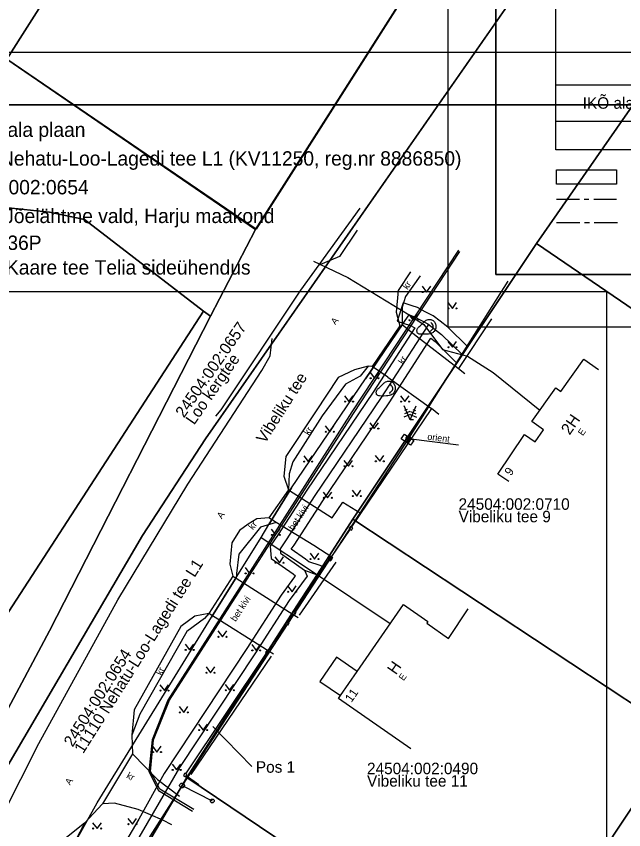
# Model space of a CAD drawing. Extents: x 553261 to 553443, y 6588794 to 6589074.
# Drawn here: x 553293.2 to 553356.6, y 6588861 to 6588946 of the extents above; entities that cross this region are included whole.
import ezdxf

# ---------------------------------------------------------------- set-up
doc = ezdxf.new("R2010")
doc.units = 0
for name, color, linetype in [('AED', 7, 'Continuous'), ('ELRAJATISMP', 7, 'Continuous'), ('HALJASTUS', 7, 'Continuous'), ('HOONE', 7, 'Continuous'), ('KASUTUSALA', 7, 'Continuous'), ('KPKAABEL', 7, 'Continuous'), ('MPKAABEL', 7, 'Continuous'), ('MPOHULIIN', 7, 'Continuous'), ('PIIR', 7, 'Continuous'), ('POST', 7, 'Continuous'), ('PR_SIDE', 7, 'Continuous'), ('PUU', 7, 'Continuous'), ('RELJEEF', 7, 'Continuous'), ('SITRASS', 7, 'Continuous'), ('TEE', 7, 'Continuous'), ('VORMISTUS', 7, 'Continuous'), ('VORMISTUS_1', 7, 'Continuous')]:
    doc.layers.add(name, color=color, linetype=linetype)

msp = doc.modelspace()

# ---------------------------------------------------------------- linework, layer by layer
at = {"layer": 'AED'}
for p, q in [((553326.069, 6588889.475), (553328.034, 6588892.392)), ((553325.826, 6588889.268), (553322.211, 6588883.814)), ((553321.522, 6588882.688), (553322.095, 6588883.54)), ((553319.487, 6588879.704), (553321.369, 6588882.436))]:
    msp.add_line(p, q, dxfattribs=at)
for points in [[(553342.795, 6588914.398), (553339.341, 6588909.194), (553339.996, 6588908.689)], [(553337.306, 6588904.401), (553336.512, 6588905.044), (553328.161, 6588892.658)], [(553319.28, 6588879.489), (553310.86, 6588866.886)], [(553310.919, 6588866.683), (553312.224, 6588865.754)]]:
    msp.add_lwpolyline(points, dxfattribs=at)
for points in [[(553328.057, 6588892.72), (553327.907, 6588892.467), (553328.16, 6588892.317), (553328.31, 6588892.57)], [(553325.947, 6588889.573), (553325.75, 6588889.33), (553325.994, 6588889.133), (553326.19, 6588889.376)], [(553321.969, 6588883.617), (553322.122, 6588883.868), (553322.373, 6588883.715), (553322.22, 6588883.464)], [(553321.244, 6588882.513), (553321.397, 6588882.764), (553321.648, 6588882.611), (553321.495, 6588882.36)], [(553319.386, 6588879.785), (553319.2, 6588879.553), (553319.401, 6588879.392), (553319.587, 6588879.623)], [(553310.768, 6588866.938), (553310.621, 6588866.68), (553310.845, 6588866.553), (553310.992, 6588866.811)]]:
    msp.add_lwpolyline(points, close=True, dxfattribs=at)
at = {"layer": 'ELRAJATISMP'}
for p, q in [((553334.079, 6588902.102), (553333.742, 6588901.609)), ((553334.303, 6588901.948), (553333.966, 6588901.456))]:
    msp.add_line(p, q, dxfattribs=at)
msp.add_lwpolyline([(553333.699, 6588902.363), (553334.684, 6588901.687), (553334.346, 6588901.195), (553333.361, 6588901.87)], close=True, dxfattribs=at)
at = {"layer": 'HALJASTUS'}
for p, q in [((553335.545, 6588917.799), (553336.008, 6588917.192)), ((553336.008, 6588917.192), (553336.454, 6588917.799)), ((553338.245, 6588916.088), (553338.708, 6588915.481)), ((553338.708, 6588915.481), (553339.154, 6588916.088)), ((553334.165, 6588914.857), (553334.628, 6588914.25)), ((553334.628, 6588914.25), (553335.074, 6588914.857)), ((553338.245, 6588912.035), (553338.708, 6588911.429)), ((553338.708, 6588911.429), (553339.154, 6588912.035)), ((553330.115, 6588908.793), (553330.578, 6588908.187)), ((553330.578, 6588908.187), (553331.024, 6588908.793)), ((553327.445, 6588906.362), (553327.908, 6588905.755)), ((553327.908, 6588905.755), (553328.354, 6588906.362)), ((553333.295, 6588906.362), (553333.758, 6588905.755)), ((553333.758, 6588905.755), (553334.204, 6588906.362)), ((553330.085, 6588903.54), (553330.548, 6588902.934)), ((553330.548, 6588902.934), (553330.994, 6588903.54)), ((553325.435, 6588903.21), (553325.898, 6588902.603)), ((553325.898, 6588902.603), (553326.344, 6588903.21)), ((553323.185, 6588900.088), (553323.648, 6588899.481)), ((553323.648, 6588899.481), (553324.094, 6588900.088)), ((553330.655, 6588900.118), (553331.118, 6588899.512)), ((553331.118, 6588899.512), (553331.564, 6588900.118)), ((553327.385, 6588899.608), (553327.848, 6588899.001)), ((553327.848, 6588899.001), (553328.294, 6588899.608)), ((553328.255, 6588896.486), (553328.718, 6588895.879)), ((553328.718, 6588895.879), (553329.164, 6588896.486)), ((553325.225, 6588896.306), (553325.688, 6588895.699)), ((553325.688, 6588895.699), (553326.134, 6588896.306)), ((553319.795, 6588892.434), (553320.258, 6588891.827)), ((553320.258, 6588891.827), (553320.704, 6588892.434)), ((553323.845, 6588889.912), (553324.308, 6588889.305)), ((553324.308, 6588889.305), (553324.754, 6588889.912)), ((553320.185, 6588889.522), (553320.648, 6588888.915)), ((553320.648, 6588888.915), (553321.094, 6588889.522)), ((553326.535, 6588888.988), (553322.728, 6588883.445)), ((553317.065, 6588888.411), (553317.528, 6588887.804)), ((553317.528, 6588887.804), (553317.974, 6588888.411)), ((553321.505, 6588886.49), (553321.968, 6588885.883)), ((553321.968, 6588885.883), (553322.414, 6588886.49)), ((553314.235, 6588881.789), (553314.698, 6588881.182)), ((553314.698, 6588881.182), (553315.144, 6588881.789)), ((553310.804, 6588880.425), (553311.268, 6588879.818)), ((553311.268, 6588879.818), (553311.713, 6588880.425)), ((553317.763, 6588880.369), (553318.227, 6588879.762)), ((553318.227, 6588879.762), (553318.672, 6588880.369)), ((553319.797, 6588879.161), (553311.403, 6588866.807)), ((553312.986, 6588878.038), (553313.449, 6588877.431)), ((553313.449, 6588877.431), (553313.895, 6588878.038)), ((553308.175, 6588876.172), (553308.638, 6588875.566)), ((553308.638, 6588875.566), (553309.084, 6588876.172)), ((553314.991, 6588876.208), (553315.454, 6588875.601)), ((553315.454, 6588875.601), (553315.9, 6588876.208)), ((553310.193, 6588873.89), (553310.656, 6588873.284)), ((553310.656, 6588873.284), (553311.102, 6588873.89)), ((553312.219, 6588872.047), (553312.682, 6588871.44)), ((553312.682, 6588871.44), (553313.128, 6588872.047)), ((553307.4, 6588869.743), (553307.863, 6588869.137)), ((553307.863, 6588869.137), (553308.309, 6588869.743)), ((553309.446, 6588867.886), (553309.91, 6588867.279)), ((553309.91, 6588867.279), (553310.355, 6588867.886)), ((553301.15, 6588861.764), (553301.613, 6588861.158)), ((553301.613, 6588861.158), (553302.059, 6588861.764)), ((553304.837, 6588862.218), (553305.3, 6588861.612)), ((553305.3, 6588861.612), (553305.746, 6588862.218))]:
    msp.add_line(p, q, dxfattribs=at)
for centre in [(553335.607, 6588917.192), (553336.436, 6588917.192), (553338.307, 6588915.481), (553339.136, 6588915.481), (553334.227, 6588914.25), (553335.056, 6588914.25), (553338.307, 6588911.429), (553339.136, 6588911.429), (553330.177, 6588908.187), (553331.006, 6588908.187), (553327.507, 6588905.755), (553328.336, 6588905.755), (553333.357, 6588905.755), (553334.186, 6588905.755), (553325.497, 6588902.603), (553326.326, 6588902.603), (553330.147, 6588902.934), (553330.976, 6588902.934), (553323.247, 6588899.481), (553324.076, 6588899.481), (553327.447, 6588899.001), (553328.276, 6588899.001), (553330.717, 6588899.512), (553331.546, 6588899.512), (553325.287, 6588895.699), (553326.116, 6588895.699), (553328.317, 6588895.879), (553329.146, 6588895.879), (553319.857, 6588891.827), (553320.686, 6588891.827), (553320.247, 6588888.915), (553321.076, 6588888.915), (553323.907, 6588889.305), (553324.736, 6588889.305), (553317.127, 6588887.804), (553317.956, 6588887.804), (553321.567, 6588885.883), (553322.396, 6588885.883), (553314.297, 6588881.182), (553315.126, 6588881.182), (553310.867, 6588879.818), (553311.696, 6588879.818), (553317.826, 6588879.762), (553318.654, 6588879.762), (553313.048, 6588877.431), (553313.877, 6588877.431), (553308.237, 6588875.566), (553309.066, 6588875.566), (553315.053, 6588875.601), (553315.882, 6588875.601), (553310.255, 6588873.284), (553311.084, 6588873.284), (553312.281, 6588871.44), (553313.11, 6588871.44), (553307.462, 6588869.137), (553308.291, 6588869.137), (553309.509, 6588867.279), (553310.337, 6588867.279), (553304.899, 6588861.612), (553305.728, 6588861.612), (553301.212, 6588861.158), (553302.041, 6588861.158)]:
    msp.add_circle(centre, 0.055, dxfattribs=at)
at = {"layer": 'HOONE'}
for points in [[(553344.6, 6588897.4), (553343.46, 6588898.16), (553346.25, 6588902.3), (553347.34, 6588901.56), (553348.22, 6588902.8), (553347, 6588903.67), (553349.51, 6588907.19), (553350.03, 6588906.81), (553352.44, 6588910.18), (553353.95, 6588909.1)], [(553334.38, 6588869.47), (553326.81, 6588874.73), (553327.02, 6588875.04), (553328.78, 6588877.57), (553333.6, 6588884.54), (553336.16, 6588882.78), (553336.03, 6588882.6), (553338.31, 6588881.02), (553340.37, 6588884.09)], [(553328.78, 6588877.57), (553326.61, 6588879.07), (553324.87, 6588876.53), (553327.02, 6588875.04)]]:
    msp.add_lwpolyline(points, dxfattribs=at)
at = {"layer": 'KASUTUSALA'}
msp.add_lwpolyline([(553298.589, 6588845.489), (553310.97, 6588866.48), (553318.933, 6588878.873), (553322.486, 6588884.402), (553325.143, 6588888.536), (553324.915, 6588888.615), (553323.722, 6588889.029), (553323.368, 6588889.281), (553321.889, 6588890.331), (553322.183, 6588890.765), (553325.191, 6588895.396), (553332.108, 6588905.636), (553336.471, 6588912.361), (553336.92, 6588912.017), (553339.047, 6588909.917), (553339.184, 6588909.781), (553340.314, 6588911.477), (553338.236, 6588913.528), (553337.435, 6588914.141), (553336.697, 6588914.706), (553335.876, 6588915.141), (553335.06, 6588915.573), (553334.508, 6588915.751), (553333.556, 6588916.059), (553332.941, 6588914.156), (553333.892, 6588913.849), (553334.278, 6588913.724), (553334.794, 6588913.451), (553330.44, 6588906.74), (553323.524, 6588896.5), (553320.516, 6588891.87), (553319.681, 6588890.636), (553319.806, 6588889.357), (553322.069, 6588887.75), (553322.329, 6588887.566), (553322.229, 6588887.43), (553320.837, 6588885.535), (553317.258, 6588879.965), (553308.612, 6588866.907), (553305.976, 6588862.143), (553296.944, 6588846.829)], dxfattribs=at)
at = {"layer": 'KPKAABEL'}
for points in [[(553339.343, 6588921.581), (553328.2, 6588904.67), (553309, 6588874.55), (553307.35, 6588870.42), (553307.02, 6588867.11), (553308.01, 6588865.12), (553311.573, 6588862.96)], [(553311.706, 6588863.143), (553308.18, 6588865.28), (553307.18, 6588867.11), (553307.51, 6588870.42), (553309.17, 6588874.55), (553328.37, 6588904.51), (553339.504, 6588921.413)]]:
    msp.add_lwpolyline(points, dxfattribs=at)
at = {"layer": 'MPKAABEL'}
msp.add_line((553334.121, 6588901.885), (553339.337, 6588901.229), dxfattribs=at)
msp.add_lwpolyline([(553329.039, 6588925.972), (553322.846, 6588917.405), (553314.535, 6588904.876), (553313.983, 6588904.237)], dxfattribs=at)
msp.add_lwpolyline([(553329.039, 6588925.972), (553322.846, 6588917.405), (553314.535, 6588904.876), (553313.983, 6588904.237)], dxfattribs=at)
at = {"layer": 'MPOHULIIN'}
msp.add_lwpolyline([(553344.514, 6588918.326), (553334.121, 6588901.885), (553310.484, 6588865.652), (553295.163, 6588841.482), (553297.428, 6588840.466)], dxfattribs=at)
at = {"layer": 'PIIR'}
for points in [[(553269.61, 6588823.387), (553275.1, 6588838.43), (553306.34, 6588891.77), (553312.93, 6588901.87), (553404.2, 6589032.89), (553408.34, 6589040.49)], [(553431.953, 6589028.538), (553426.41, 6589023.65), (553416.94, 6589023.42), (553405.24, 6589006.54), (553386.47, 6588978.82), (553366.97, 6588950.29), (553347.5, 6588922.26), (553328.32, 6588893.48), (553310.97, 6588866.48), (553295.9, 6588840.93), (553293.3, 6588836.47), (553287.77, 6588819.195)], [(553400.72, 6589027.895), (553312.93, 6588901.87), (553306.34, 6588891.77), (553275.1, 6588838.43), (553278.46, 6588847.64), (553296.63, 6588881.81), (553313.47, 6588914.66), (553318.15, 6588923.71), (553343.84, 6588964.11), (553353.8, 6588979.04), (553383.89, 6589024.22), (553386.338, 6589027.895)], [(553269.61, 6588964.599), (553291.21, 6588997.51), (553317.25, 6588980.99), (553292.18, 6588941.51), (553269.61, 6588957.599)], [(553269.61, 6588957.599), (553292.18, 6588941.51), (553318.15, 6588923.71), (553313.47, 6588914.66), (553312.72, 6588915.18), (553300.31, 6588924.76), (553296.64, 6588925.52), (553288.66, 6588926.39), (553273.87, 6588927.17), (553269.61, 6588927.473)], [(553269.61, 6588852.643), (553283.01, 6588869.39), (553312.72, 6588915.18), (553313.47, 6588914.66), (553296.63, 6588881.81), (553278.46, 6588847.64), (553269.61, 6588823.387)], [(553321.735, 6588819.195), (553313.8, 6588823.92), (553293.3, 6588836.47), (553295.9, 6588840.93), (553310.97, 6588866.48), (553344.52, 6588843.86), (553348.48, 6588841.22), (553333.312, 6588819.195)]]:
    msp.add_lwpolyline(points, dxfattribs=at)
for points in [[(553343.85, 6588964.09), (553318.22, 6588923.75), (553292.18, 6588941.51), (553317.25, 6588980.99)], [(553401.3, 6588927.47), (553381.71, 6588898.9), (553347.5, 6588922.26), (553366.97, 6588950.29)], [(553273.87, 6588927.17), (553288.66, 6588926.39), (553296.64, 6588925.52), (553300.31, 6588924.76), (553312.72, 6588915.18), (553283.01, 6588869.39), (553270.78, 6588864.58)], [(553347.5, 6588922.26), (553381.71, 6588898.9), (553362.44, 6588870.9), (553328.32, 6588893.48)], [(553362.44, 6588870.9), (553344.52, 6588843.86), (553310.97, 6588866.48), (553328.32, 6588893.48)], [(553362.44, 6588870.9), (553393.72, 6588849.46), (553375.51, 6588823.13), (553344.52, 6588843.86)]]:
    msp.add_lwpolyline(points, close=True, dxfattribs=at)
at = {"layer": 'POST'}
msp.add_lwpolyline([(553310.484, 6588865.652), (553313.644, 6588864.04)], dxfattribs=at)
for centre, radius in [((553334.121, 6588901.885), 0.25), ((553310.484, 6588865.652), 0.25), ((553313.644, 6588864.04), 0.2)]:
    msp.add_circle(centre, radius, dxfattribs=at)
at = {"layer": 'PR_SIDE'}
for points in [[(553334.2, 6588914.8), (553334.669, 6588914.648), (553336.156, 6588913.861)], [(553336.156, 6588913.861), (553336.152, 6588913.706), (553331.274, 6588906.188), (553324.358, 6588895.948), (553321.349, 6588891.317), (553320.712, 6588890.375), (553320.757, 6588889.908), (553323.26, 6588888.131)], [(553336.156, 6588913.861), (553337.578, 6588912.772), (553339.749, 6588910.629)], [(553323.26, 6588888.131), (553323.539, 6588887.524), (553321.662, 6588884.968), (553318.096, 6588879.419), (553310.213, 6588867.527), (553305.363, 6588859.136), (553297.678, 6588846.105), (553295.174, 6588844.041), (553294.134, 6588842.531), (553294.155, 6588836.433), (553294.55, 6588836.03), (553295.658, 6588835.332), (553307.558, 6588828.466)], [(553323.26, 6588888.131), (553324.587, 6588887.671)]]:
    msp.add_lwpolyline(points, dxfattribs=at)
at = {"layer": 'PUU'}
for p, q in [((553334.298, 6588903.859), (553333.677, 6588905.307)), ((553334.002, 6588904.929), (553333.726, 6588904.811)), ((553334.298, 6588903.859), (553334.919, 6588905.307)), ((553334.594, 6588904.929), (553334.869, 6588904.811)), ((553334.298, 6588904.403), (553333.641, 6588904.122)), ((553334.258, 6588904.713), (553333.707, 6588904.476)), ((553334.298, 6588904.403), (553334.954, 6588904.122)), ((553334.337, 6588904.713), (553334.889, 6588904.476)), ((553334.658, 6588903.859), (553334.298, 6588903.859))]:
    msp.add_line(p, q, dxfattribs=at)
at = {"layer": 'RELJEEF'}
for points in [[(553335.004, 6588913.178), (553335.023, 6588913.253), (553335.044, 6588913.318), (553335.067, 6588913.372), (553335.097, 6588913.429), (553335.148, 6588913.499), (553335.21, 6588913.562), (553335.296, 6588913.639), (553335.433, 6588913.765), (553335.523, 6588913.854), (553335.651, 6588913.986), (553335.723, 6588914.057), (553335.82, 6588914.141), (553335.896, 6588914.196), (553335.984, 6588914.25), (553336.093, 6588914.301), (553336.182, 6588914.327), (553336.278, 6588914.339), (553336.362, 6588914.335), (553336.448, 6588914.319), (553336.525, 6588914.295), (553336.625, 6588914.247), (553336.687, 6588914.208), (553336.769, 6588914.14), (553336.825, 6588914.08), (553336.883, 6588913.998), (553336.916, 6588913.936), (553336.948, 6588913.855), (553336.971, 6588913.771), (553336.983, 6588913.689), (553336.988, 6588913.605), (553336.985, 6588913.513), (553336.971, 6588913.418), (553336.946, 6588913.328), (553336.907, 6588913.234), (553336.865, 6588913.16), (553336.811, 6588913.087), (553336.752, 6588913.022), (553336.696, 6588912.974), (553336.623, 6588912.924), (553336.537, 6588912.881), (553336.463, 6588912.854), (553336.361, 6588912.828), (553336.225, 6588912.808), (553336.068, 6588912.793), (553335.77, 6588912.78), (553335.508, 6588912.779), (553335.351, 6588912.785), (553335.256, 6588912.798), (553335.183, 6588912.821), (553335.124, 6588912.853), (553335.077, 6588912.898), (553335.043, 6588912.954), (553335.021, 6588913.031), (553335.009, 6588913.106), (553335.004, 6588913.178)], [(553336.389, 6588913.048), (553336.432, 6588913.094), (553336.5, 6588913.167), (553336.568, 6588913.24), (553336.636, 6588913.314), (553336.692, 6588913.396), (553336.717, 6588913.492), (553336.717, 6588913.592), (553336.696, 6588913.689), (553336.654, 6588913.78), (553336.591, 6588913.857), (553336.525, 6588913.933), (553336.459, 6588914.008)], [(553330.763, 6588906.733), (553330.781, 6588906.807), (553330.803, 6588906.873), (553330.825, 6588906.926), (553330.856, 6588906.983), (553330.907, 6588907.054), (553330.969, 6588907.117), (553331.055, 6588907.194), (553331.192, 6588907.319), (553331.282, 6588907.409), (553331.41, 6588907.54), (553331.482, 6588907.612), (553331.579, 6588907.696), (553331.654, 6588907.75), (553331.743, 6588907.804), (553331.851, 6588907.855), (553331.941, 6588907.882), (553332.037, 6588907.893), (553332.12, 6588907.889), (553332.207, 6588907.873), (553332.283, 6588907.849), (553332.384, 6588907.802), (553332.445, 6588907.763), (553332.527, 6588907.695), (553332.584, 6588907.634), (553332.641, 6588907.552), (553332.674, 6588907.49), (553332.707, 6588907.409), (553332.729, 6588907.325), (553332.742, 6588907.244), (553332.747, 6588907.159), (553332.743, 6588907.068), (553332.729, 6588906.972), (553332.705, 6588906.883), (553332.666, 6588906.788), (553332.623, 6588906.714), (553332.57, 6588906.641), (553332.51, 6588906.577), (553332.455, 6588906.528), (553332.381, 6588906.479), (553332.296, 6588906.435), (553332.221, 6588906.408), (553332.119, 6588906.382), (553331.984, 6588906.362), (553331.826, 6588906.348), (553331.529, 6588906.334), (553331.266, 6588906.333), (553331.11, 6588906.339), (553331.015, 6588906.353), (553330.942, 6588906.375), (553330.883, 6588906.407), (553330.835, 6588906.452), (553330.802, 6588906.509), (553330.779, 6588906.586), (553330.768, 6588906.66), (553330.763, 6588906.733)], [(553332.148, 6588906.603), (553332.19, 6588906.648), (553332.259, 6588906.721), (553332.327, 6588906.794), (553332.394, 6588906.868), (553332.45, 6588906.95), (553332.476, 6588907.046), (553332.476, 6588907.146), (553332.455, 6588907.244), (553332.413, 6588907.334), (553332.35, 6588907.412), (553332.284, 6588907.487), (553332.218, 6588907.562)]]:
    msp.add_lwpolyline(points, dxfattribs=at)
at = {"layer": 'SITRASS'}
for points in [[(553324.215, 6588920.405), (553327.78, 6588918.72), (553334.2, 6588914.8)], [(553307.558, 6588828.466), (553295.66, 6588835.33), (553294.1, 6588838.54), (553291.17, 6588844.39), (553295.69, 6588853.22), (553301.63, 6588863.85), (553313.57, 6588883.23), (553316.033, 6588887.218), (553318.75, 6588891.56), (553319.542, 6588892.899), (553321.928, 6588896.745), (553329.641, 6588908.12), (553333.547, 6588913.882), (553334.2, 6588914.8)], [(553334.2, 6588914.8), (553335.72, 6588913.81), (553337.68, 6588911.19), (553340.28, 6588910.48), (553342.96, 6588908.8), (553347.833, 6588904.838)], [(553333.547, 6588913.882), (553329.641, 6588908.12)], [(553321.928, 6588896.745), (553319.542, 6588892.899)], [(553318.75, 6588891.56), (553323.99, 6588888.07), (553332.229, 6588882.557)], [(553316.033, 6588887.218), (553313.57, 6588883.23)]]:
    msp.add_lwpolyline(points, dxfattribs=at)
at = {"layer": 'TEE'}
for q in [(553330.34, 6588909.412), (553336.512, 6588905.044)]:
    msp.add_line((553331.956, 6588908.316), q, dxfattribs=at)
for points in [[(553328.762, 6588923.648), (553326.911, 6588920.91), (553324.706, 6588919.982)], [(553334.329, 6588919.291), (553333.04, 6588917.355), (553332.85, 6588915.093), (553333.222, 6588913.67), (553330.34, 6588909.412), (553329.924, 6588909.448), (553328.499, 6588909.084), (553326.788, 6588908.27), (553324.413, 6588904.676), (553321.337, 6588900.007), (553321.118, 6588897.967), (553321.608, 6588896.537), (553319.538, 6588893.615), (553318.296, 6588893.515), (553317.4, 6588892.958), (553316.492, 6588892.302), (553315.673, 6588891), (553315.47, 6588888.775), (553315.77, 6588887.533), (553313.266, 6588883.627), (553311.827, 6588883.339), (553310.368, 6588882.257), (553305.487, 6588873.565), (553305.238, 6588870.895), (553305.326, 6588868.941), (553302.169, 6588863.726), (553300.291, 6588861.708), (553298.435, 6588860.23)], [(553335.343, 6588918.881), (553333.824, 6588916.723), (553333.471, 6588915.609), (553333.449, 6588913.797), (553334.941, 6588912.636)], [(553334.941, 6588912.636), (553339.341, 6588909.194)], [(553275.581, 6588820.532), (553279.746, 6588834.38), (553282.177, 6588840.718), (553284.513, 6588846.828), (553289.854, 6588858.846), (553295.527, 6588870.055), (553303.781, 6588885.053), (553311.073, 6588897.13), (553318.802, 6588908.984), (553319.679, 6588910.523), (553319.887, 6588912.345)], [(553329.924, 6588909.448), (553329.094, 6588908.4), (553327.538, 6588907.555), (553325.098, 6588904.268), (553322.037, 6588899.452), (553321.666, 6588898.19), (553321.608, 6588896.537)], [(553321.608, 6588896.537), (553326.142, 6588893.601), (553327.279, 6588895.257), (553329.08, 6588894.131), (553328.124, 6588892.68)], [(553320.302, 6588893.12), (553318.665, 6588892.651), (553316.417, 6588889.808), (553316.18, 6588887.808), (553316.124, 6588887.312)], [(553326.219, 6588889.422), (553324.255, 6588890.727), (553320.302, 6588893.12), (553319.538, 6588893.615)], [(553315.77, 6588887.533), (553316.124, 6588887.312), (553322.096, 6588883.506), (553322.617, 6588883.182)], [(553313.266, 6588883.627), (553312.843, 6588883.095), (553310.974, 6588881.745), (553306.085, 6588873.105), (553305.238, 6588870.895)], [(553320.043, 6588879.362), (553319.596, 6588879.659), (553313.266, 6588883.627)], [(553305.326, 6588868.941), (553307.935, 6588866.286), (553310.236, 6588864.523)], [(553309.407, 6588861.552), (553308.478, 6588862.039), (553305.916, 6588863.129), (553303.439, 6588863.789), (553302.169, 6588863.726)], [(553300.291, 6588861.708), (553296.943, 6588855.275), (553292.377, 6588844.334), (553292.084, 6588842.869)]]:
    msp.add_lwpolyline(points, dxfattribs=at)
at = {"layer": 'VORMISTUS'}
msp.add_line((553313.694, 6588871.799), (553317.77, 6588867.65), dxfattribs=at)
for points in [[(553261.045, 6588942.264), (553366.045, 6588942.264), (553366.045, 6588793.764), (553261.045, 6588793.764)], [(553266.045, 6588799.264), (553361.045, 6588799.264), (553361.045, 6588936.764), (553266.045, 6588936.764)], [(553266.045, 6588936.764), (553361.045, 6588936.764), (553361.045, 6588799.264), (553266.045, 6588799.264)], [(553354.795, 6588812.264), (553272.295, 6588812.264), (553272.295, 6588917.264), (553354.795, 6588917.264)]]:
    msp.add_lwpolyline(points, close=True, dxfattribs=at)
at = {"layer": 'VORMISTUS_1'}
for p, q in [((553349.505, 6588935.04), (553432.005, 6588935.04)), ((553349.596, 6588926.901), (553351.971, 6588926.901)), ((553352.471, 6588926.901), (553352.971, 6588926.901)), ((553353.471, 6588926.901), (553355.846, 6588926.901)), ((553349.596, 6588924.447), (553352.018, 6588924.447)), ((553352.518, 6588924.447), (553353.018, 6588924.447)), ((553353.518, 6588924.447), (553355.939, 6588924.447))]:
    msp.add_line(p, q, dxfattribs=at)
for points in [[(553338.255, 6589062.04), (553443.255, 6589062.04), (553443.255, 6588913.54), (553338.255, 6588913.54)], [(553343.255, 6588919.04), (553438.255, 6588919.04), (553438.255, 6589056.54), (553343.255, 6589056.54)], [(553343.255, 6589056.54), (553438.255, 6589056.54), (553438.255, 6588919.04), (553343.255, 6588919.04)], [(553432.005, 6588932.04), (553349.505, 6588932.04), (553349.505, 6589037.04), (553432.005, 6589037.04)], [(553349.505, 6588938.84), (553432.005, 6588938.84), (553432.005, 6588932.04), (553349.505, 6588932.04)], [(553349.596, 6588929.973), (553355.846, 6588929.973), (553355.846, 6588928.473), (553349.596, 6588928.473)]]:
    msp.add_lwpolyline(points, close=True, dxfattribs=at)

# ---------------------------------------------------------------- texts
at = {"layer": 'HOONE'}
for s, height, rotation, p in [('2H', 1.2, 55.41411, (553350.949, 6588902.194)), ('E', 0.7, 55.41411, (553352.333, 6588902.121)), ('9', 0.9, 55.97783, (553344.823, 6588897.938)), ('H', 1.2, 55.41411, (553332.806, 6588877.143)), ('E', 0.7, 55.41411, (553333.624, 6588876.533)), ('11', 0.9, 55.12988, (553328.171, 6588874.27))]:
    msp.add_text(s, height=height, rotation=rotation, dxfattribs=at).set_placement(p)
at = {"layer": 'MPKAABEL'}
msp.add_text('orient', height=0.7, rotation=352.67049, dxfattribs=at).set_placement((553336.064, 6588901.769))
at = {"layer": 'PIIR'}
for s, rotation, p in [('24504:002:0657', 55.29844, (553310.681, 6588903.985)), ('Loo kergtee', 55.29844, (553311.749, 6588903.245)), ('11110 Nehatu-Loo-Lagedi tee L1', 57.71559, (553300.162, 6588868.908)), ('24504:002:0654', 57.71559, (553299.063, 6588869.602))]:
    msp.add_text(s, height=1.2, rotation=rotation, dxfattribs=at).set_placement(p)
for s, p in [('24504:002:0710', (553339.356, 6588894.449)), ('Vibeliku tee 9', (553339.356, 6588893.149)), ('24504:002:0490', (553329.795, 6588866.83)), ('Vibeliku tee 11', (553329.795, 6588865.53))]:
    msp.add_text(s, height=1.2, dxfattribs=at).set_placement(p)
at = {"layer": 'TEE'}
for s, height, rotation, p in [('kr', 0.7, 54.83215, (553334.022, 6588917.39)), ('A', 0.7, 50.66428, (553326.488, 6588913.715)), ('kr', 0.7, 57.72807, (553333.579, 6588909.578)), ('Vibeliku tee', 1.2, 57.4994, (553319.144, 6588901.293)), ('kr', 0.7, 58.33464, (553323.729, 6588902.177)), ('bet kivi', 0.7, 56.76046, (553322.128, 6588892.218)), ('A', 0.7, 54.23588, (553314.629, 6588893.442)), ('kr', 0.7, 51.61576, (553317.893, 6588892.294)), ('bet kivi', 0.7, 56.82764, (553316.084, 6588882.709)), ('kr', 0.7, 65.52391, (553308.363, 6588877.092)), ('kr', 0.7, 330.70629, (553304.611, 6588866.484)), ('A', 0.7, 56.69591, (553298.793, 6588865.634))]:
    msp.add_text(s, height=height, rotation=rotation, dxfattribs=at).set_placement(p)
at = {"layer": 'VORMISTUS'}
for s, p in [('Isikliku kasutusõiguse ala plaan', (553272.3, 6588933.399)), ('Kinnistu nimi:  11110 Nehatu-Loo-Lagedi tee L1 (KV11250, reg.nr 8886850)', (553272.3, 6588930.399)), ('Katastritunnus: 24504:002:0654', (553272.3, 6588927.399)), ('Asukoht:  Loo alevik,  Jõelähtme vald, Harju maakond', (553272.3, 6588924.399)), ('Kirjanurk OÜ töö nr 9236P', (553272.293, 6588921.594)), ('Loo alevik, Vibeliku ja Kaare tee Telia sideühendus', (553272.255, 6588919.02))]:
    msp.add_text(s, height=1.5, rotation=360, dxfattribs=at).set_placement(p)
msp.add_text('Pos 1', height=1.2, dxfattribs=at).set_placement((553318.192, 6588866.984))
at = {"layer": 'VORMISTUS_1'}
msp.add_text('IKÕ ala pos nr', height=1.2, dxfattribs=at).set_placement((553352.315, 6588936.34))

doc.saveas('drawing.dxf')
